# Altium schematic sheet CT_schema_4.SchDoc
size 350 x 214 mm
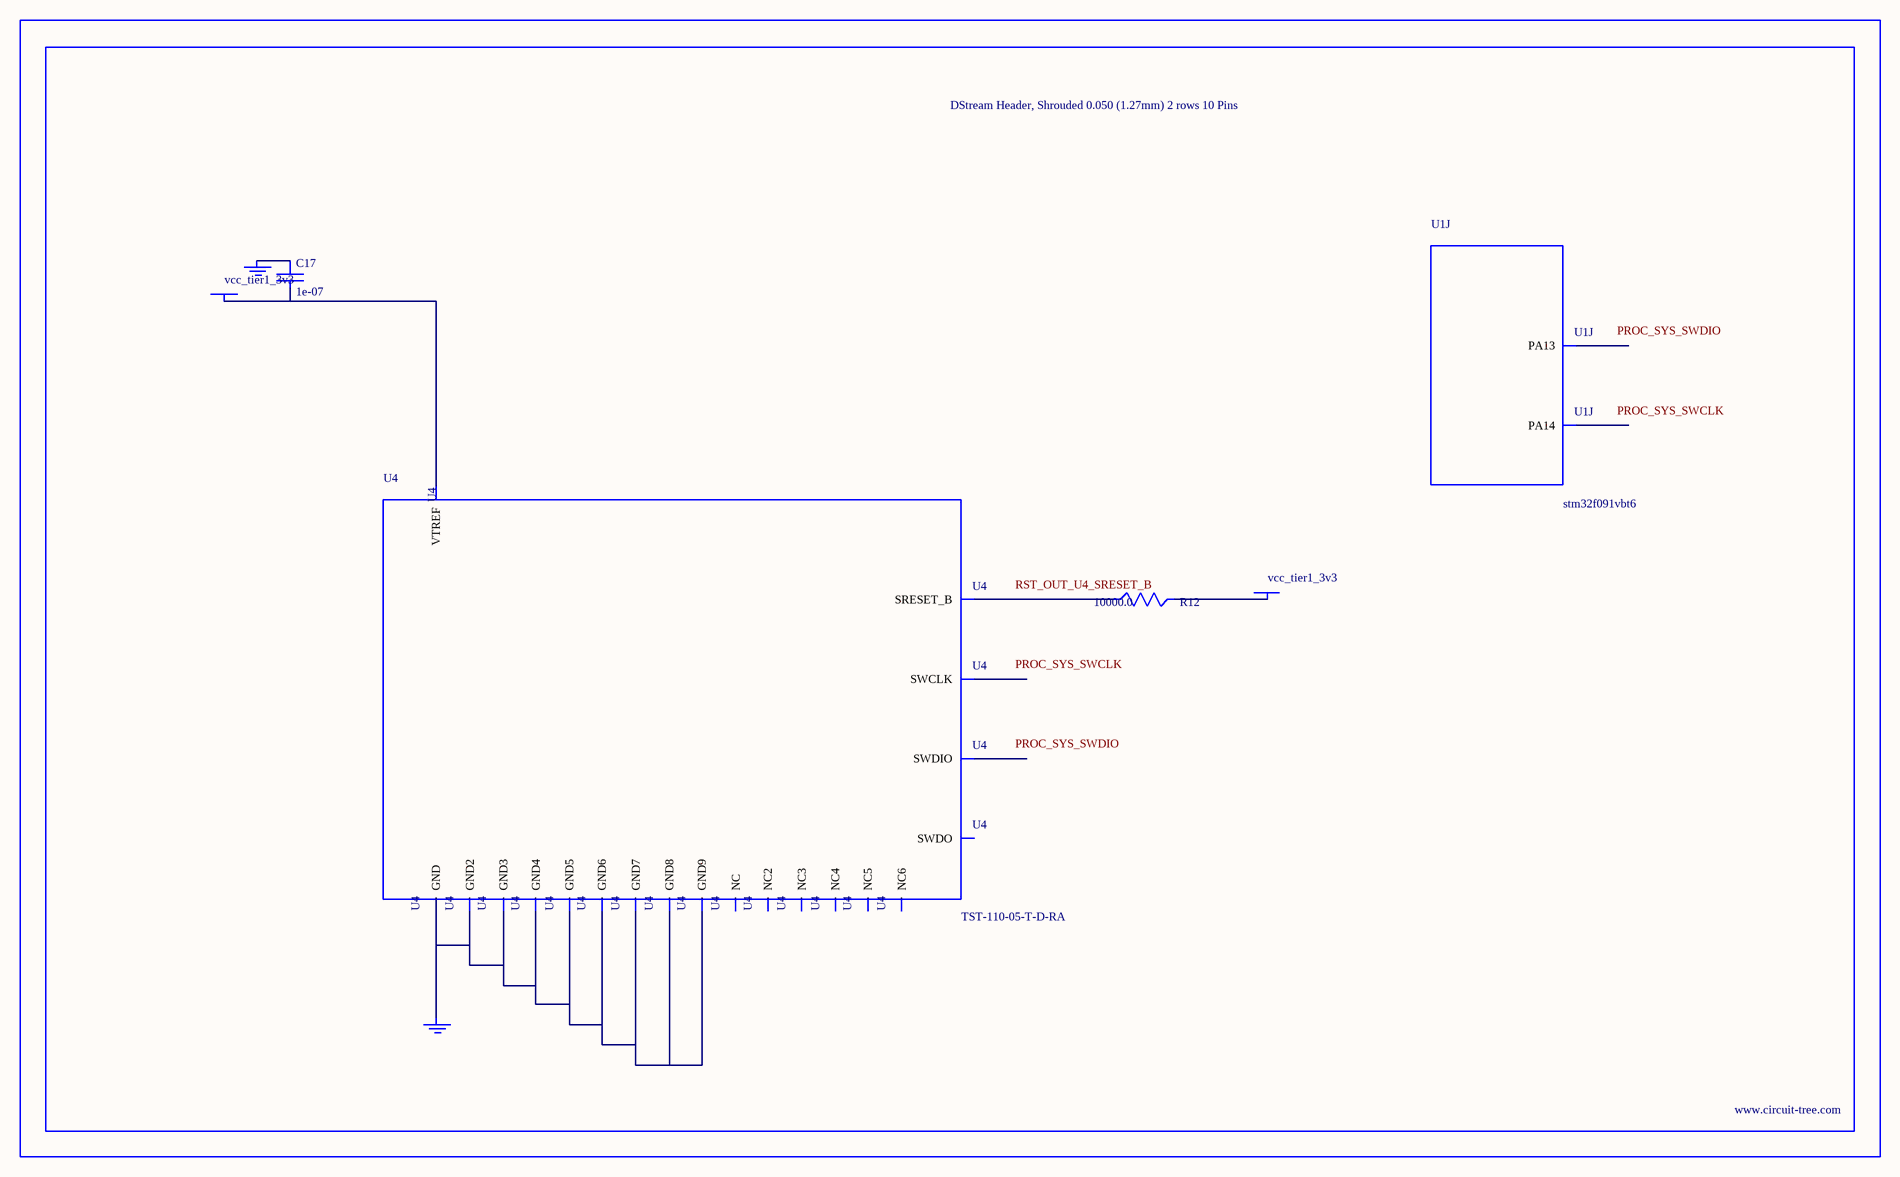
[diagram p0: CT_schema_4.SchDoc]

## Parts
BORDER3  (no value)
C17  1e-07  [C0402]
GND_INSTANCE_3_0  (no value)
GND_INSTANCE_3_1  (no value)
POWER_INSTANCE_3_0  vcc_tier1_3v3
POWER_INSTANCE_3_1  vcc_tier1_3v3
R12  10000.0  [R0603]
U1  stm32f091vbt6  [LQFP100]  (part J of 10)
U4  TST-110-05-T-D-RA  [TST-110-05-T-D-RA]

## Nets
NetC17_1: C17.1 GND_INSTANCE_3_0.0(GND)
NetC17_2: C17.2 POWER_INSTANCE_3_0.0(PWR) U4.1(VTREF)
NetGND_INSTANCE_3_1_0: GND_INSTANCE_3_1.0(GND) U4.4(GND) U4.6(GND2) U4.8(GND3) U4.10(GND4) U4.12(GND5) U4.14(GND6) U4.16(GND7) U4.18(GND8) U4.20(GND9)
NetPOWER_INSTANCE_3_1_0: POWER_INSTANCE_3_1.0(PWR) R12.2
NetR12_1: R12.1 U4.15(SRESET_B)

Not connected (* = marked no-connect by the designer): U1 72(PA13) 76(PA14); U4 2(NC) 3(NC2) 5(NC3) 7(SWDIO) 9(SWCLK) 11(NC4) 13(SWDO) 17(NC5) 19(NC6)

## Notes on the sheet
- Labels drawn without touching a wire or pin: PROC_SYS_SWCLK, PROC_SYS_SWDIO, RST_OUT_U4_SRESET_B

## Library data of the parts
BORDER3 = BORDER_PAGE3
C17 = C0402C104K3RACTU
GND_INSTANCE_3_0 GND_INSTANCE_3_1 = GND
POWER_INSTANCE_3_0 POWER_INSTANCE_3_1 = PWR
R12 = RC0603JR-0710KL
